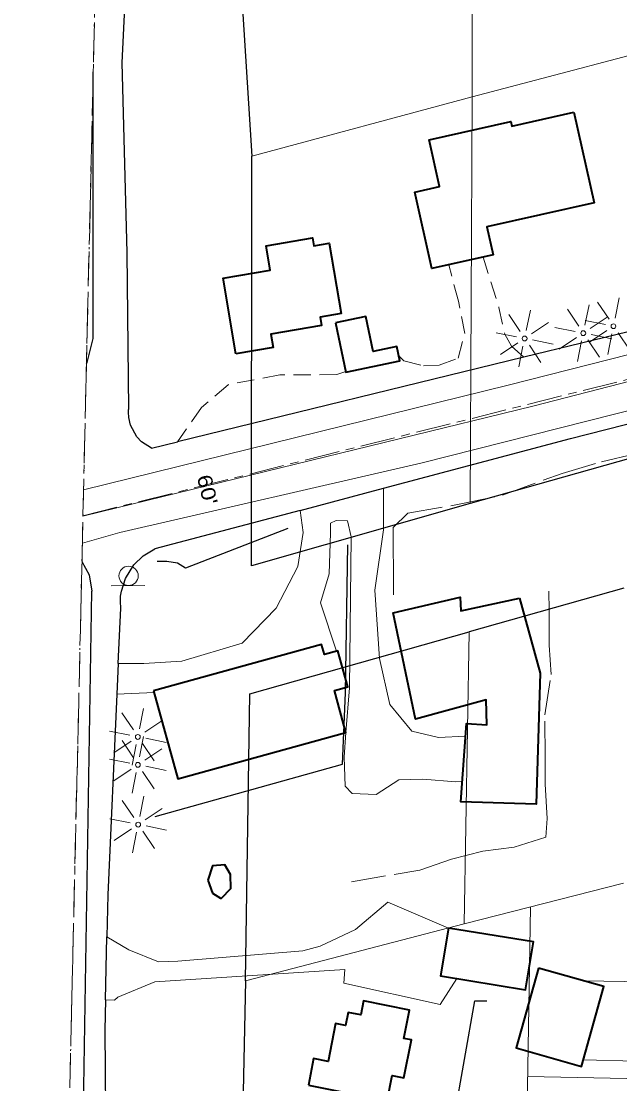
# Model space of a CAD drawing. Extents: x -861682 to -858969, y -1797841 to -1795153.
# Drawn here: x -861676.7 to -861428.5, y -1796923.4 to -1796482.7 of the extents above; entities that cross this region are included whole.
import ezdxf

# ---------------------------------------------------------------- set-up
doc = ezdxf.new("R2010")
doc.units = 0
doc.header["$LTSCALE"] = 2.4
for name, pattern in [('DOT_DASHED', [7.7, 5, -1.2, 0.3, -1.2]), ('LONG_DASH_SHORT_DASH', [9.9, 6, -1.2, 1.5, -1.2]), ('LONG_DASHED', [7.5, 6, -1.5]), ('MEDIUM_DASHED', [4.5, 3, -1.5])]:
    doc.linetypes.add(name, pattern=pattern)
for name, color, linetype, lineweight in [('10', 7, 'Continuous', 25), ('11', 7, 'Continuous', 13), ('12', 7, 'Continuous', 35), ('14', 7, 'Continuous', 25), ('17', 7, 'Continuous', 13), ('21', 7, 'Continuous', 13), ('30', 7, 'Continuous', 13), ('32', 7, 'LONG_DASH_SHORT_DASH', 13), ('42', 7, 'Continuous', 25), ('52', 7, 'LONG_DASHED', 13), ('54', 7, 'Continuous', 13), ('61', 7, 'Continuous', 13)]:
    doc.layers.add(name, color=color, linetype=linetype, lineweight=lineweight)
doc.layers.add('43', color=7, linetype='Continuous')

msp = doc.modelspace()

# ---------------------------------------------------------------- linework, layer by layer
at = {"layer": '10'}
for p, q in [((-861420.498, -1796610.385), (-861468.282, -1796622.069)), ((-861468.282, -1796622.069), (-861611.881, -1796657.181)), ((-861622.716, -1796659.831), (-861611.881, -1796657.181)), ((-861561.056, -1796685.61), (-861526.485, -1796676.428)), ((-861561.056, -1796685.61), (-861621.368, -1796701.628)), ((-861636.485, -1796749.17), (-861635.439, -1796726.244)), ((-861636.485, -1796749.17), (-861637.067, -1796761.906)), ((-861641.79, -1796888.674), (-861641.235, -1796862.486))]:
    msp.add_line(p, q, dxfattribs=at)
for points in [[(-861632.978, -1796456.776), (-861634.93, -1796500.001), (-861632.961, -1796578.634), (-861632.226, -1796643.811)], [(-861526.485, -1796676.428), (-861448.916, -1796655.829), (-861381.048, -1796638.475), (-861363.01, -1796633.863), (-861361.24, -1796633.411), (-861348.534, -1796630.162)], [(-861622.716, -1796659.831), (-861626.9, -1796657.132), (-861628.785, -1796655.138), (-861631.416, -1796650.327), (-861632.157, -1796647.111), (-861632.279, -1796644.912), (-861632.226, -1796643.811)], [(-861635.439, -1796726.244), (-861635.589, -1796723.454), (-861635.479, -1796721.254), (-861635.17, -1796719.088), (-861633.536, -1796713.838), (-861630.067, -1796708.234), (-861626.098, -1796704.429), (-861621.368, -1796701.628)], [(-861637.067, -1796761.906), (-861640.866, -1796845.055), (-861641.235, -1796862.486)], [(-861641.79, -1796888.674), (-861642.058, -1796901.266), (-861641.695, -1796951.331)]]:
    msp.add_lwpolyline(points, dxfattribs=at)
at = {"layer": '11'}
msp.add_line((-861621.628, -1796761.201), (-861637.067, -1796761.906), dxfattribs=at)
at = {"layer": '11', "linetype": 'MEDIUM_DASHED'}
for points in [[(-861485.225, -1796580.549), (-861478.655, -1796601.395), (-861476.249, -1796612.485), (-861473.395, -1796617.433), (-861468.282, -1796622.069)], [(-861520.21, -1796621.33), (-861518.006, -1796623.516), (-861509.968, -1796625.609), (-861503.356, -1796625.347), (-861495.574, -1796622.482), (-861492.781, -1796612.315), (-861495.433, -1796598.865), (-861499.408, -1796583.731)], [(-861542.14, -1796628.019), (-861545.85, -1796629.296), (-861569.466, -1796629.39), (-861590.94, -1796633.491), (-861602.002, -1796642.982), (-861611.881, -1796657.181)]]:
    msp.add_lwpolyline(points, dxfattribs=at)
at = {"layer": '11'}
for points in [[(-861492.491, -1796779.309), (-861503.681, -1796779.797), (-861514.791, -1796777.244), (-861523.809, -1796766.18), (-861528.137, -1796747.068), (-861530.14, -1796718.737), (-861526.462, -1796693.69), (-861526.485, -1796676.428)], [(-861561.056, -1796685.61), (-861559.757, -1796694.768), (-861562.062, -1796708.947), (-861570.967, -1796726.223), (-861585.079, -1796740.685), (-861610.082, -1796748.107), (-861625.901, -1796749.115), (-861632.277, -1796749.14), (-861636.485, -1796749.17)], [(-861546.014, -1796744.022), (-861552.555, -1796724.024), (-861549.061, -1796711.965), (-861548.42, -1796694.959), (-861548.437, -1796690.944), (-861546.08, -1796689.754), (-861541.356, -1796689.971), (-861539.912, -1796696.578), (-861540.605, -1796759.163), (-861542.057, -1796777.799), (-861542.851, -1796787.984), (-861542.331, -1796800.026), (-861539.485, -1796803.085), (-861529.564, -1796803.517), (-861520.142, -1796797.339), (-861510.224, -1796797.063), (-861496.523, -1796798.189), (-861493.782, -1796798.027)], [(-861499.577, -1796858.851), (-861524.661, -1796848.131), (-861538.077, -1796859.52), (-861552.691, -1796866.428), (-861560.004, -1796868.346), (-861611.708, -1796872.569), (-861619.736, -1796872.837), (-861632.036, -1796867.927), (-861641.235, -1796862.486)], [(-861496.137, -1796879.827), (-861503, -1796890.553), (-861542.947, -1796881.739), (-861542.497, -1796876.069), (-861621.356, -1796881.11), (-861636.681, -1796887.548), (-861638.093, -1796888.734), (-861641.79, -1796888.674)], [(-861408.319, -1796884.423), (-861410.412, -1796893.25), (-861412.763, -1796895.857), (-861418.199, -1796894.935), (-861418.254, -1796881.237), (-861443.628, -1796880.735)], [(-861443.61, -1796913.508), (-861421.901, -1796914.079), (-861401.823, -1796914.943), (-861342.913, -1796922.043)]]:
    msp.add_lwpolyline(points, dxfattribs=at)
at = {"layer": '12'}
for points in [[(-861447.569, -1796520.502), (-861439.153, -1796558.018), (-861483.637, -1796567.997), (-861481.032, -1796579.609), (-861506.433, -1796585.307), (-861513.547, -1796553.594), (-861503.241, -1796551.282), (-861507.592, -1796531.889), (-861473.74, -1796524.294), (-861473.296, -1796526.273)], [(-861587.684, -1796620.724), (-861593.006, -1796589.336), (-861573.487, -1796586.026), (-861575.211, -1796575.859), (-861555.928, -1796572.589), (-861555.367, -1796575.898), (-861548.97, -1796574.813), (-861544.031, -1796603.931), (-861552.764, -1796605.412), (-861552.171, -1796608.91), (-861573.143, -1796612.465), (-861572.188, -1796618.097)], [(-861546.408, -1796607.806), (-861542.074, -1796628.335), (-861519.727, -1796623.617), (-861520.997, -1796617.602), (-861530.743, -1796619.66), (-861533.808, -1796605.145)], [(-861470.14, -1796722.038), (-861461.514, -1796753.176), (-861463.185, -1796807.501), (-861494.363, -1796806.445), (-861492.131, -1796774.081), (-861483.628, -1796774.52), (-861483.905, -1796764.13), (-861513.157, -1796772.276), (-861522.544, -1796728.152), (-861494.703, -1796721.664), (-861494.444, -1796727.33)], [(-861621.84, -1796760.432), (-861611.774, -1796796.997), (-861542.056, -1796777.804), (-861546.87, -1796760.319), (-861541.35, -1796758.799), (-861545.461, -1796743.87), (-861551.017, -1796745.4), (-861552.163, -1796741.238)], [(-861599.325, -1796838.983), (-861597.414, -1796844.407), (-861594.099, -1796846.52), (-861593.627, -1796846.518), (-861589.865, -1796842.488), (-861589.888, -1796836.584), (-861592.266, -1796832.579), (-861597.46, -1796833.072)], [(-861499.584, -1796858.892), (-861502.811, -1796878.743), (-861467.555, -1796884.474), (-861464.328, -1796864.622)], [(-861462.202, -1796875.508), (-861471.516, -1796908.608), (-861444.38, -1796916.244), (-861435.066, -1796883.144)], [(-861557.655, -1796924.07), (-861525.038, -1796930.551), (-861522.953, -1796920.056), (-861518.03, -1796921.034), (-861514.896, -1796905.256), (-861518.03, -1796904.633), (-861515.701, -1796892.917), (-861534.817, -1796889.117), (-861535.959, -1796894.86), (-861541.116, -1796893.835), (-861542.194, -1796899.257), (-861546.355, -1796898.43), (-861549.481, -1796914.158), (-861555.449, -1796912.972)]]:
    msp.add_lwpolyline(points, close=True, dxfattribs=at)
at = {"layer": '14'}
for points in [[(-861566.14, -1796693.14), (-861608.583, -1796709.606), (-861611.898, -1796707.494), (-861616.388, -1796706.803), (-861620.402, -1796706.819)], [(-861621.159, -1796812.622), (-861543.548, -1796790.82), (-861542.25, -1796761.295), (-861541.316, -1796699.89)], [(-861507.944, -1796953.155), (-861507.972, -1796946.307), (-861506.101, -1796941.812), (-861501.388, -1796939.196), (-861497.143, -1796937.762), (-861488.6, -1796889.078), (-861485.53, -1796889.066), (-861483.64, -1796889.058)]]:
    msp.add_lwpolyline(points, dxfattribs=at)
at = {"layer": '17'}
for p, q in [((-861430.495, -1796605.874), (-861428.769, -1796597.474)), ((-861467.316, -1796610.981), (-861465.59, -1796602.581)), ((-861445.46, -1796609.218), (-861450.25, -1796602.09)), ((-861443, -1796608.758), (-861441.274, -1796600.358)), ((-861432.955, -1796606.334), (-861437.745, -1796599.206)), ((-861469.776, -1796611.441), (-861474.566, -1796604.313)), ((-861434.455, -1796608.534), (-861442.917, -1796606.86)), ((-861440.8, -1796610.158), (-861433.704, -1796605.418)), ((-861465.116, -1796612.381), (-861458.02, -1796607.641)), ((-861446.96, -1796611.418), (-861455.422, -1796609.744)), ((-861433.915, -1796611.034), (-861441.141, -1796615.89)), ((-861471.276, -1796613.641), (-861479.738, -1796611.967)), ((-861464.676, -1796614.901), (-861456.196, -1796616.625)), ((-861446.42, -1796613.918), (-861453.646, -1796618.774)), ((-861446.04, -1796623.878), (-861444.36, -1796615.278)), ((-861441.7, -1796614.818), (-861436.9, -1796622.032)), ((-861440.36, -1796612.678), (-861431.88, -1796614.402)), ((-861433.535, -1796620.994), (-861431.855, -1796612.394)), ((-861429.195, -1796611.934), (-861424.395, -1796619.148)), ((-861470.736, -1796616.141), (-861477.962, -1796620.997)), ((-861470.356, -1796626.101), (-861468.676, -1796617.501)), ((-861466.016, -1796617.041), (-861461.216, -1796624.255)), ((-861630.176, -1796776.688), (-861634.966, -1796769.56)), ((-861627.716, -1796776.228), (-861625.99, -1796767.828)), ((-861625.516, -1796777.628), (-861618.42, -1796772.888)), ((-861631.676, -1796778.888), (-861640.138, -1796777.214)), ((-861631.136, -1796781.388), (-861638.362, -1796786.244)), ((-861630.13, -1796788.26), (-861634.92, -1796781.132)), ((-861630.756, -1796791.348), (-861629.076, -1796782.748)), ((-861627.67, -1796787.8), (-861625.944, -1796779.4)), ((-861626.416, -1796782.288), (-861621.616, -1796789.502)), ((-861625.076, -1796780.148), (-861616.596, -1796781.872)), ((-861625.47, -1796789.2), (-861618.374, -1796784.46)), ((-861631.63, -1796790.46), (-861640.092, -1796788.786)), ((-861625.03, -1796791.72), (-861616.55, -1796793.444)), ((-861631.09, -1796792.96), (-861638.316, -1796797.816)), ((-861630.71, -1796802.92), (-861629.03, -1796794.32)), ((-861626.37, -1796793.86), (-861621.57, -1796801.074)), ((-861627.57, -1796812.597), (-861625.844, -1796804.197)), ((-861630.03, -1796813.057), (-861634.82, -1796805.929)), ((-861625.37, -1796813.997), (-861618.274, -1796809.257)), ((-861631.53, -1796815.257), (-861639.992, -1796813.583)), ((-861630.99, -1796817.757), (-861638.216, -1796822.613)), ((-861626.27, -1796818.657), (-861621.47, -1796825.871)), ((-861624.93, -1796816.517), (-861616.45, -1796818.241)), ((-861630.61, -1796827.717), (-861628.93, -1796819.117))]:
    msp.add_line(p, q, dxfattribs=at)
for centre in [(-861443.66, -1796612.118), (-861431.155, -1796609.234), (-861467.976, -1796614.341), (-861628.376, -1796779.588), (-861628.33, -1796791.16), (-861628.23, -1796815.957)]:
    msp.add_circle(centre, 1, dxfattribs=at)
at = {"layer": '21'}
msp.add_line((-861625.425, -1796716.804), (-861639.429, -1796716.858), dxfattribs=at)
msp.add_circle((-861632.187, -1796712.771), 4, dxfattribs=at)
at = {"layer": '30'}
for p, q in [((-861489.939, -1796343.018), (-861489.711, -1796514.077)), ((-861581.116, -1796538.693), (-861489.711, -1796514.077)), ((-861490.532, -1796682.793), (-861489.711, -1796514.077)), ((-861491.02, -1796735.935), (-861492.993, -1796857.056)), ((-861427.024, -1796840.227), (-861492.993, -1796857.056)), ((-861465.508, -1796850.044), (-861480.985, -1797800.155)), ((-861583.726, -1796880.798), (-861492.993, -1796857.056)), ((-861328.164, -1796923.166), (-861466.655, -1796920.485))]:
    msp.add_line(p, q, dxfattribs=at)
msp.add_lwpolyline([(-861489.711, -1796514.077), (-861393.124, -1796488.603), (-861300.148, -1796463.638), (-861202.355, -1796436.746), (-861109.061, -1796410.798)], dxfattribs=at)
at = {"layer": '32'}
for points in [[(-861635.972, -1796031.868), (-861668.34, -1797434.932), (-861671.877, -1797797.365)], [(-861651.105, -1796687.844), (-861333.558, -1796608.31), (-860734.009, -1796456.297), (-860402.78, -1796372.876), (-860279.286, -1796339.345), (-860213.04, -1796323.806), (-860166.423, -1796315.627), (-860126.348, -1796310.72), (-860089.545, -1796308.267), (-860056.831, -1796312.356), (-859995.492, -1796331.984), (-859827.834, -1796395.777), (-859764.042, -1796414.588), (-859688.8, -1796435.852), (-859629.915, -1796444.03), (-859562.034, -1796449.756), (-859471.253, -1796448.938), (-859395.193, -1796443.213), (-859240.62, -1796421.131), (-859002.083, -1796383.657)]]:
    msp.add_lwpolyline(points, dxfattribs=at)
at = {"layer": '42'}
for p, q in [((-861646.87, -1796614.327), (-861646.858, -1796503.749)), ((-861646.858, -1796503.749), (-861646.858, -1796503.741)), ((-861395.174, -1796655.867), (-861490.532, -1796682.793)), ((-861651.202, -1796957.407), (-861647.476, -1796719.081)), ((-861426.818, -1796717.913), (-861491.02, -1796735.935)), ((-861583.726, -1796880.798), (-861585.789, -1796986.257))]:
    msp.add_line(p, q, dxfattribs=at)
for points in [[(-861489.939, -1796343.018), (-861592.302, -1796361.775), (-861581.116, -1796538.693)], [(-861490.532, -1796682.793), (-861581.25, -1796708.619), (-861581.116, -1796538.693)], [(-861649.648, -1796624.706), (-861649.371, -1796624.292), (-861646.87, -1796614.327)], [(-861651.542, -1796706.783), (-861648.552, -1796712.371), (-861647.476, -1796719.081)], [(-861583.726, -1796880.798), (-861581.878, -1796761.719), (-861491.02, -1796735.935)]]:
    msp.add_lwpolyline(points, dxfattribs=at)
at = {"layer": '52'}
for points in [[(-861522.339, -1796720.595), (-861522.383, -1796709.732), (-861522.415, -1796701.703), (-861522.451, -1796692.729), (-861516.335, -1796686.8), (-861494.387, -1796682.933), (-861477.161, -1796679.322), (-861452.401, -1796670.249), (-861436.124, -1796665.46), (-861401.441, -1796657.292), (-861381.62, -1796653.197)], [(-861539.81, -1796839.69), (-861511.489, -1796834.853), (-861498.282, -1796830.313), (-861485.307, -1796826.955), (-861472.325, -1796825.249), (-861459.116, -1796821.182), (-861458.675, -1796813.387), (-861459.44, -1796799.22), (-861459.488, -1796787.413), (-861459.556, -1796770.409), (-861457.025, -1796753.632), (-861457.782, -1796741.59), (-861457.84, -1796727.185), (-861457.872, -1796719.156)]]:
    msp.add_lwpolyline(points, dxfattribs=at)
at = {"layer": '54'}
for points in [[(-860172.631, -1796317.253), (-860204.018, -1796322.811), (-860236.107, -1796330.26), (-860268.193, -1796338.182), (-860308.776, -1796347.556), (-860380.023, -1796366.026), (-860439.712, -1796381.144), (-860499.871, -1796396.736), (-860533.844, -1796405.374), (-860583.86, -1796418.091), (-860653.219, -1796436.08), (-860743.108, -1796458.404), (-860803.739, -1796473.997), (-860915.799, -1796503.257), (-861038.012, -1796533.031), (-861123.178, -1796555.335), (-861206.46, -1796575.979), (-861319.702, -1796605.009), (-861464.557, -1796642.43), (-861630.889, -1796683.009), (-861651.109, -1796688.034)], [(-861650.857, -1796677.096), (-861474.746, -1796633.733), (-861214.288, -1796567.508), (-861003.138, -1796513.526)], [(-861031.589, -1796544.577), (-861065.327, -1796552.978), (-861114.398, -1796565.691), (-861162.535, -1796575.803), (-861238.02, -1796597.596), (-861316.585, -1796616.804), (-861510.986, -1796665.997), (-861635.801, -1796694.837), (-861651.366, -1796699.153)]]:
    msp.add_lwpolyline(points, dxfattribs=at)
at = {"layer": '61', "linetype": 'DOT_DASHED'}
msp.add_line((-861615.801, -1795157.51), (-861676.699, -1797797.295), dxfattribs=at)

# ---------------------------------------------------------------- texts
at = {"layer": '43', "width": 1.2}
msp.add_text("60'", height=6, rotation=283.596, dxfattribs=at).set_placement((-861603.913, -1796671.63))

doc.saveas('drawing.dxf')
